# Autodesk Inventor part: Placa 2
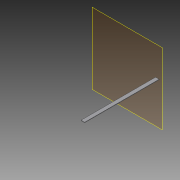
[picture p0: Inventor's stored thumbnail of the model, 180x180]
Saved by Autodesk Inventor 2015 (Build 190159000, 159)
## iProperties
Created: 2015-04
Part Number: Placa 2
Material: Generic
Document SubType Name: Modeling
Designer: suporte
Density: 1 g/cm^3
Appearance: Default
Author: suporte
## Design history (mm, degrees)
workplane "Work Plane1"
sketch "Sketch1"
  geometry: L1 (-175.237, 900)-(-187.737, 900); L2 (-187.737, 900)-(-187.737, 800); L3 (-187.737, 800)-(-175.237, 800); L4 (-175.237, 800)-(-175.237, 900); L5 (912.5, 900)-(-912.5, 900) reference; L6 (-187.737, 900)-(-187.737, 800) reference; 1 further point
  constraints: 8 end point, 2 parallel, 2 point on line, 1 horizontal, 1 perpendicular
  dimensions: "d0" = 12.5 distance of L3.end L2.end; "d1" = 100 distance of L1.end L2.end
extrude "Extrusion1" new body sketch "Sketch1" distance "d2" = 2100; taper "d3" = 0 deg
body "Solid1"
node "Reference1"
node "Reference2"
